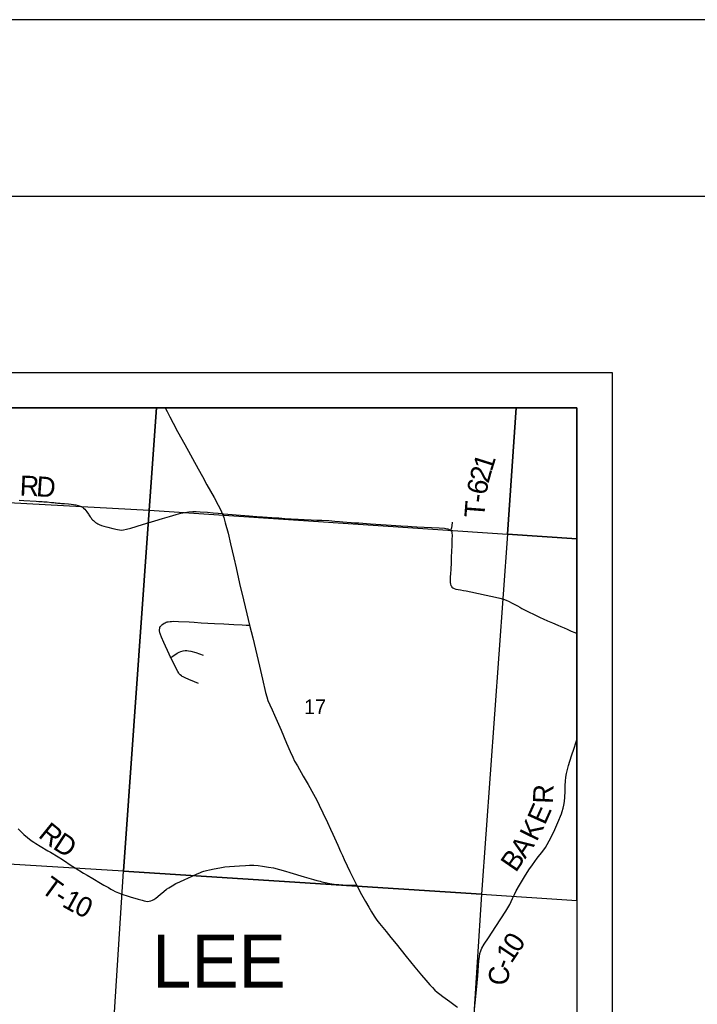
# Model space of a CAD drawing. Extents: x 0 to 34, y 0 to 22.
# Drawn here: x 7.32 to 9.241, y 19.209 to 22 of the extents above; entities that cross this region are included whole.
import ezdxf

# ---------------------------------------------------------------- set-up
doc = ezdxf.new("R2010")
doc.units = 0
for name, color, linetype in [('GM_X_Corporation', 7, 'Continuous'), ('GM_X_County_Road', 7, 'Continuous'), ('GM_X_County_Road_Text', 7, 'Continuous'), ('GM_X_Section_Text', 7, 'Continuous'), ('GM_X_State_Route', 7, 'Continuous'), ('GM_X_Township_Road', 7, 'Continuous'), ('GM_X_Township_Road_Text', 7, 'Continuous'), ('GM_X_Township_Text', 7, 'Continuous'), ('SH_Border', 7, 'Continuous'), ('SH_Cut_Line', 7, 'Continuous'), ('SH_Data', 7, 'Continuous')]:
    doc.layers.add(name, color=color, linetype=linetype)

msp = doc.modelspace()

# ---------------------------------------------------------------- linework, layer by layer
at = {"layer": 'GM_X_Corporation'}
for points in [[(7.7078, 20.9), (6.6786, 20.9), (6.6629, 20.6653), (7.6877, 20.6095)], [(8.7279, 20.9), (7.7078, 20.9), (7.6877, 20.6095), (8.7029, 20.5418)], [(8.9, 20.5284), (8.9, 20.9), (8.7279, 20.9), (8.7029, 20.5418)], [(6.6629, 20.6653), (7.6877, 20.6095), (7.6147, 19.5863), (6.5914, 19.6486)], [(7.6877, 20.6095), (8.7029, 20.5418), (8.6299, 19.5205), (7.6147, 19.5863)], [(8.9, 19.5025), (8.9, 20.5284), (8.7029, 20.5418), (8.6299, 19.5205)], [(7.6147, 19.5863), (8.6299, 19.5205), (8.6049, 19.1351), (8.5816, 18.7382), (8.5636, 18.5025), (7.9912, 18.537), (7.548, 18.5656), (7.5613, 18.7776), (7.5889, 19.1863)]]:
    msp.add_lwpolyline(points, close=True, dxfattribs=at)
at = {"layer": 'GM_X_County_Road'}
msp.add_lwpolyline([(8.61, 19.1947), (8.6135, 19.231), (8.617, 19.269), (8.619, 19.2886), (8.6214, 19.3194), (8.6222, 19.3317), (8.6235, 19.3444), (8.6248, 19.3523), (8.6256, 19.3555), (8.6263, 19.3574), (8.6285, 19.3627), (8.6309, 19.3679), (8.6371, 19.3789), (8.649, 19.3969), (8.6704, 19.429), (8.6984, 19.473), (8.7094, 19.4919), (8.7176, 19.5089), (8.7227, 19.5202), (8.7277, 19.5301), (8.737, 19.5462), (8.7518, 19.5697), (8.7641, 19.5893), (8.7736, 19.604), (8.7874, 19.6228), (8.8032, 19.6428), (8.8105, 19.6529), (8.8159, 19.6613), (8.8217, 19.6716), (8.8297, 19.6878), (8.8371, 19.7043), (8.8455, 19.7243), (8.8561, 19.7489), (8.8585, 19.7553), (8.8611, 19.7644), (8.8631, 19.7735), (8.8646, 19.7834), (8.8656, 19.7958), (8.8663, 19.8114), (8.8669, 19.8286), (8.8677, 19.841), (8.8687, 19.8522), (8.8705, 19.8627), (8.8732, 19.8745), (8.8763, 19.8858), (8.885, 19.913), (8.8922, 19.9348), (8.8971, 19.9496), (8.9, 19.9583)], dxfattribs=at)
at = {"layer": 'GM_X_State_Route'}
for points in [[(7.7325, 20.9), (7.7382, 20.8889), (7.7455, 20.8745), (7.7554, 20.8558), (7.7679, 20.8329), (7.7882, 20.7958), (7.8262, 20.7267), (7.8383, 20.705), (7.8513, 20.6817), (7.8716, 20.6453), (7.8831, 20.624), (7.8905, 20.6091), (7.8946, 20.5998), (7.8952, 20.5983), (7.8988, 20.5884), (7.9032, 20.5736), (7.9109, 20.5441), (7.9183, 20.514), (7.9273, 20.4746), (7.934, 20.4456), (7.9439, 20.402), (7.955, 20.3548), (7.9645, 20.3155), (7.9722, 20.2832), (7.9808, 20.2471), (8.0003, 20.1669), (8.0089, 20.13), (8.0175, 20.0925), (8.0208, 20.0798), (8.0242, 20.0697), (8.0291, 20.0576), (8.0356, 20.0434), (8.0426, 20.0282), (8.0612, 19.9855), (8.0769, 19.9491), (8.0871, 19.9257), (8.0944, 19.9092), (8.0998, 19.8983), (8.1075, 19.8847), (8.1244, 19.8549), (8.1378, 19.8319), (8.1532, 19.8045), (8.1623, 19.7872), (8.1694, 19.7727), (8.1799, 19.7509), (8.1927, 19.7239), (8.2015, 19.7055), (8.2079, 19.6913), (8.2219, 19.6595), (8.2301, 19.6414), (8.235, 19.6307), (8.2402, 19.6194), (8.2485, 19.6014), (8.256, 19.585), (8.2693, 19.5583), (8.2752, 19.5469)], [(8.2752, 19.5469), (8.2893, 19.5197), (8.3007, 19.5001), (8.3098, 19.4841), (8.3173, 19.4708), (8.3249, 19.4584), (8.3332, 19.4467), (8.3405, 19.4375), (8.3589, 19.4148), (8.3726, 19.398), (8.3877, 19.3798), (8.4162, 19.3436), (8.4404, 19.3134), (8.4591, 19.2914), (8.4714, 19.2774), (8.4828, 19.2642), (8.4903, 19.2559), (8.4973, 19.2488), (8.5042, 19.2425), (8.5109, 19.237), (8.5199, 19.2304), (8.5393, 19.2168), (8.5589, 19.2027), (8.5612, 19.2008)]]:
    msp.add_lwpolyline(points, dxfattribs=at)
at = {"layer": 'GM_X_Township_Road'}
for points in [[(7.3193, 20.6374), (7.3323, 20.6368), (7.367, 20.6348), (7.3744, 20.6344), (7.3836, 20.6339), (7.3884, 20.6335), (7.398, 20.6327), (7.4109, 20.6315), (7.4175, 20.6308), (7.4211, 20.6304), (7.4241, 20.63), (7.4282, 20.6296), (7.43, 20.6295), (7.4355, 20.629), (7.4391, 20.6288), (7.4475, 20.6281), (7.4587, 20.627), (7.4663, 20.6262), (7.4791, 20.6243), (7.4863, 20.6226), (7.4921, 20.6206), (7.498, 20.6178), (7.5015, 20.6154), (7.5051, 20.6122), (7.5082, 20.6084), (7.5106, 20.6049), (7.5153, 20.5978), (7.5163, 20.5963), (7.52, 20.5907), (7.5218, 20.5883), (7.5225, 20.5873), (7.524, 20.5853), (7.5265, 20.5825), (7.5291, 20.5799), (7.531, 20.5782), (7.5329, 20.5766), (7.5355, 20.5748), (7.5392, 20.5725), (7.5423, 20.5706), (7.5457, 20.5689), (7.5526, 20.566), (7.5586, 20.5642), (7.5701, 20.5613), (7.5839, 20.5579), (7.5972, 20.5546), (7.6034, 20.5535), (7.6077, 20.5532), (7.6146, 20.5538), (7.6232, 20.5554), (7.6352, 20.5585), (7.668, 20.5684), (7.7033, 20.5793), (7.7247, 20.5856), (7.7447, 20.5918), (7.7636, 20.5976), (7.7768, 20.6009), (7.7883, 20.6031), (7.7999, 20.6046), (7.811, 20.6054), (7.8209, 20.6055), (7.832, 20.605), (7.8531, 20.6034), (7.8692, 20.6019), (7.8828, 20.6008), (7.8946, 20.5998), (7.8977, 20.5995), (7.9107, 20.5984), (7.9465, 20.5955), (7.9707, 20.5937), (7.9923, 20.5919), (8.0084, 20.5906), (8.0348, 20.5888), (8.0545, 20.5876), (8.0715, 20.5863), (8.0897, 20.5851), (8.1096, 20.5838), (8.1271, 20.5831), (8.1469, 20.5822), (8.163, 20.5814), (8.1766, 20.5808), (8.1964, 20.5797), (8.2138, 20.5787), (8.2274, 20.5776), (8.2366, 20.5767), (8.2599, 20.5747), (8.2698, 20.5739), (8.2815, 20.5732), (8.315, 20.5711), (8.3591, 20.5683), (8.4006, 20.5655), (8.4204, 20.5641), (8.4309, 20.5633), (8.4457, 20.5623), (8.4667, 20.5611), (8.4878, 20.5602), (8.5094, 20.5593), (8.5242, 20.5581), (8.5288, 20.5575), (8.5341, 20.5565), (8.5382, 20.5548), (8.5422, 20.5522), (8.5442, 20.5498), (8.5452, 20.5468), (8.5457, 20.5442), (8.5461, 20.5386), (8.5457, 20.525), (8.545, 20.507), (8.5445, 20.4939), (8.5438, 20.4748), (8.5431, 20.4587), (8.5423, 20.4444), (8.5412, 20.4271), (8.541, 20.4227), (8.5406, 20.4121), (8.5409, 20.4047), (8.5418, 20.3998), (8.543, 20.3963), (8.5444, 20.3936), (8.5458, 20.3916), (8.5484, 20.3892), (8.552, 20.3874), (8.5568, 20.3859), (8.563, 20.3846), (8.5699, 20.3833), (8.5786, 20.3818), (8.5861, 20.3806), (8.5994, 20.378), (8.6428, 20.3686), (8.6693, 20.3627), (8.6817, 20.3598), (8.6919, 20.3571), (8.6993, 20.3546), (8.7076, 20.3505), (8.7147, 20.3467), (8.7311, 20.338), (8.7379, 20.3343), (8.7441, 20.3309), (8.7512, 20.3273), (8.7573, 20.3241), (8.7645, 20.3204), (8.7767, 20.3143), (8.786, 20.3095), (8.796, 20.3049), (8.8046, 20.3012), (8.8168, 20.296), (8.8309, 20.2897), (8.8458, 20.2833), (8.8548, 20.2793), (8.8635, 20.2754), (8.8719, 20.2719), (8.8838, 20.2667), (8.8941, 20.2623), (8.9, 20.2597)], [(8.5422, 20.5522), (8.5433, 20.5541), (8.5449, 20.5573), (8.5458, 20.5606), (8.5465, 20.5654), (8.5473, 20.5753)], [(7.8274, 20.118), (7.8163, 20.1226), (7.7996, 20.1295), (7.7893, 20.1337), (7.7833, 20.1365), (7.7808, 20.138), (7.7787, 20.1394), (7.7751, 20.1427), (7.7728, 20.1454), (7.7712, 20.1478), (7.7685, 20.1524), (7.765, 20.159), (7.7544, 20.18), (7.75, 20.1888), (7.7484, 20.192), (7.7469, 20.1949), (7.7437, 20.2016), (7.7287, 20.2346), (7.722, 20.2492), (7.7191, 20.2567), (7.7182, 20.2595), (7.7178, 20.2613), (7.7173, 20.2637), (7.717, 20.2656), (7.7168, 20.2671), (7.7168, 20.2687), (7.7167, 20.2704), (7.7169, 20.2725), (7.7172, 20.2744), (7.718, 20.2771), (7.719, 20.2793), (7.72, 20.2808), (7.7217, 20.2828), (7.7229, 20.284), (7.7262, 20.2867), (7.7299, 20.289), (7.7329, 20.2904), (7.7356, 20.2915), (7.7385, 20.2924), (7.7417, 20.2931), (7.7468, 20.2938), (7.7508, 20.2942), (7.7559, 20.2944), (7.7701, 20.2941), (7.8005, 20.2924), (7.8148, 20.2915), (7.8346, 20.2904), (7.8725, 20.2883), (7.8991, 20.287), (7.9276, 20.2855), (7.9512, 20.284), (7.9624, 20.2836), (7.9722, 20.2832)], [(7.7484, 20.192), (7.7544, 20.1959), (7.7665, 20.2036), (7.7725, 20.2068), (7.7771, 20.2087), (7.7836, 20.2105), (7.7891, 20.2114), (7.7916, 20.2116), (7.7941, 20.2116), (7.799, 20.2111), (7.8057, 20.2097), (7.8194, 20.2057), (7.8402, 20.1986)], [(7.316, 19.7062), (7.3223, 19.6995), (7.3322, 19.6901), (7.3429, 19.681), (7.3486, 19.6764), (7.356, 19.671), (7.36, 19.6684)], [(7.36, 19.6684), (7.3664, 19.6642), (7.3785, 19.6565), (7.4003, 19.6435), (7.4073, 19.6394), (7.4294, 19.6267), (7.442, 19.6187), (7.4692, 19.6003), (7.4776, 19.595), (7.5009, 19.5807), (7.5116, 19.5742), (7.5272, 19.5654), (7.5492, 19.5523), (7.559, 19.5467), (7.5717, 19.5394), (7.5789, 19.5351), (7.5843, 19.532), (7.5913, 19.5286), (7.6005, 19.5248), (7.6128, 19.5203), (7.625, 19.5156), (7.636, 19.5124), (7.6463, 19.5097), (7.6559, 19.5069), (7.6678, 19.5033), (7.6732, 19.5019), (7.678, 19.5009), (7.6822, 19.5003), (7.6877, 19.5007), (7.6925, 19.5017), (7.697, 19.5035), (7.7008, 19.5056), (7.7067, 19.5099), (7.7186, 19.5197), (7.729, 19.5284), (7.7368, 19.5345), (7.7429, 19.5389), (7.7524, 19.5448), (7.7633, 19.5508), (7.7739, 19.5559), (7.7887, 19.5624), (7.7972, 19.5662), (7.8096, 19.5719), (7.8231, 19.5781), (7.8311, 19.5816), (7.8368, 19.5839), (7.842, 19.5858), (7.8503, 19.588), (7.8587, 19.5901), (7.8719, 19.5929), (7.8877, 19.5957), (7.9019, 19.598), (7.9152, 19.5994), (7.9289, 19.6002), (7.9438, 19.6014), (7.9606, 19.6024), (7.9717, 19.6027), (7.984, 19.6029), (7.996, 19.6021), (8.0085, 19.6005), (8.0256, 19.5976), (8.0394, 19.595), (8.0573, 19.5906), (8.0742, 19.586), (8.0861, 19.5825), (8.1264, 19.5703), (8.1532, 19.5626), (8.1627, 19.5599), (8.1675, 19.5586), (8.1717, 19.5574), (8.1764, 19.5561), (8.1867, 19.5535), (8.2, 19.5506), (8.2121, 19.549), (8.2255, 19.548), (8.2362, 19.5473), (8.2485, 19.5465), (8.264, 19.546), (8.2713, 19.5466), (8.2752, 19.5469)]]:
    msp.add_lwpolyline(points, dxfattribs=at)
at = {"layer": 'SH_Border'}
msp.add_lwpolyline([(1.5, 21.5), (33.5, 21.5), (33.5, 0.5), (1.5, 0.5)], close=True, dxfattribs=at)
at = {"layer": 'SH_Cut_Line'}
msp.add_lwpolyline([(0, 0), (34, 0), (34, 22), (0, 22)], close=True, dxfattribs=at)
at = {"layer": 'SH_Data'}
for p, q in [((2, 21), (9, 21)), ((9, 21), (9, 14)), ((2.1, 20.9), (8.9, 20.9)), ((8.9, 20.9), (8.9, 14.1))]:
    msp.add_line(p, q, dxfattribs=at)

# ---------------------------------------------------------------- texts
at = {"layer": 'GM_X_County_Road_Text'}
for s, rotation, p in [('R', 87.7824, (8.8318, 19.7764)), ('E', 65.9004, (8.8091, 19.7147)), ('K', 63.7729, (8.786, 19.6677)), ('A', 55.585, (8.7533, 19.6188)), ('B', 55.4428, (8.7267, 19.5803)), ('0', 56.62, (8.7338, 19.3518)), ('1', 56.1988, (8.7141, 19.3223)), ('-', 69.3626, (8.7075, 19.3036)), ('C', 87.4506, (8.7063, 19.2616))]:
    msp.add_text(s, height=0.0568, rotation=rotation, dxfattribs=at).set_placement(p)
at = {"layer": 'GM_X_Section_Text'}
msp.add_text('17', height=0.04186, rotation=0, dxfattribs=at).set_placement((8.1265, 20.0312))
at = {"layer": 'GM_X_Township_Road_Text'}
for s, rotation, p in [('1', 72.4992, (8.6583, 20.7169)), ('2', 74.6892, (8.6492, 20.6837)), ('R', 357.3724, (7.3195, 20.6513)), ('D', 355.8254, (7.3657, 20.6492)), ('6', 79.0691, (8.6428, 20.6505)), ('T', 85.639, (8.6372, 20.5866)), ('-', 83.449, (8.6403, 20.6284)), ('R', 321.0415, (7.3704, 19.6844)), ('D', 326.7853, (7.4117, 19.6515)), ('T', 323.8321, (7.377, 19.5291)), ('-', 327.7845, (7.4149, 19.5017)), ('1', 330.9074, (7.4375, 19.4875)), ('0', 334.1383, (7.4712, 19.4689))]:
    msp.add_text(s, height=0.0568, rotation=rotation, dxfattribs=at).set_placement(p)
at = {"layer": 'GM_X_Township_Text'}
msp.add_text('LEE', height=0.15, rotation=0, dxfattribs=at).set_placement((7.6956, 19.2561))

doc.saveas('drawing.dxf')
